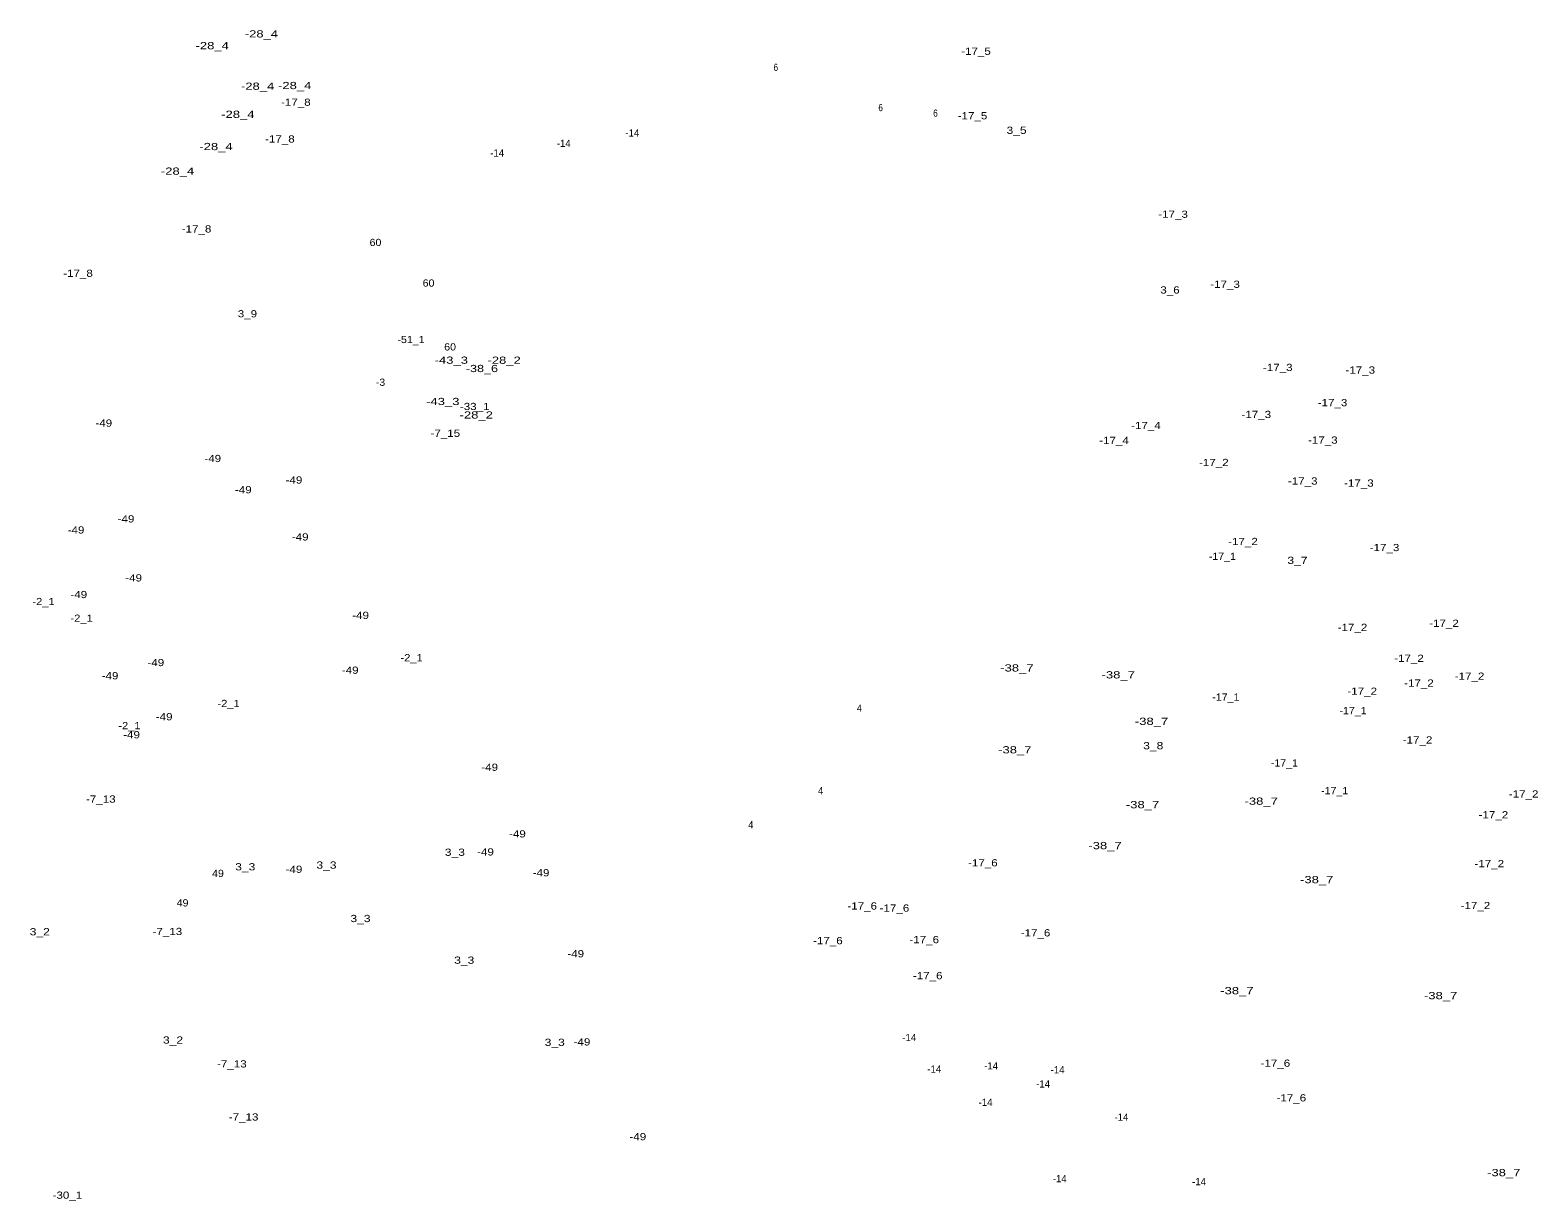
# Model space of a CAD drawing. Extents: x -663241 to -661169, y -1003538 to -1000899.
# Drawn here: x -662468 to -661633, y -1002888 to -1002239 of the extents above; entities that cross this region are included whole.
import ezdxf
from ezdxf.enums import TextEntityAlignment as Align

# ---------------------------------------------------------------- set-up
doc = ezdxf.new("R2010")
doc.units = 0
doc.header["$LTSCALE"] = 1.6
doc.layers.add('24', color=7, linetype='Continuous')

msp = doc.modelspace()

# ---------------------------------------------------------------- texts
at = {"layer": '24'}
for s, width, p in [('-28_4', 1.35, (-662340.16, -1002242.99)), ('-28_4', 1.35, (-662367.43, -1002249.52)), ('-17_5', 1.2, (-661944.33, -1002252.63)), ('6', 0.85, (-662055.2, -1002261.52)), ('-28_4', 1.35, (-662342.28, -1002271.99)), ('-28_4', 1.35, (-662321.73, -1002271.61)), ('-28_4', 1.35, (-662353.22, -1002287.55)), ('-17_8', 1.2, (-662321.11, -1002280.85)), ('6', 0.85, (-661997.15, -1002283.83)), ('6', 0.85, (-661966.78, -1002286.9)), ('-17_5', 1.2, (-661946.25, -1002288.36)), ('-17_8', 1.2, (-662329.94, -1002301.22)), ('3_5', 1.25, (-661921.84, -1002296.42)), ('-28_4', 1.35, (-662365.32, -1002305.42)), ('-28_4', 1.35, (-662386.63, -1002319.05)), ('-17_3', 1.2, (-661835.14, -1002342.92)), ('-17_8', 1.2, (-662376.11, -1002351.06)), ('60', 1.1, (-662276.99, -1002358.55)), ('-17_8', 1.2, (-662441.78, -1002375.65)), ('60', 1.1, (-662247.581, -1002381.05)), ('3_6', 1.2, (-661836.85, -1002384.88)), ('-17_3', 1.2, (-661806.34, -1002381.72)), ('3_9', 1.2, (-662347.919, -1002398.08)), ('-51_1', 1.1, (-662257.29, -1002412.34)), ('60', 1.1, (-662235.66, -1002416.44)), ('-43_3', 1.35, (-662234.99, -1002423.79)), ('-38_6', 1.3, (-662218.01, -1002428.41)), ('-28_2', 1.35, (-662205.72, -1002423.81)), ('-17_3', 1.2, (-661777.15, -1002427.82)), ('-17_3', 1.2, (-661731.45, -1002429.27)), ('-3', 1.1, (-662274.22, -1002436.01)), ('-43_3', 1.35, (-662239.7, -1002446.68)), ('-28_2', 1.35, (-662221.169, -1002454.15)), ('-33_1', 1.2, (-662222.03, -1002449.45)), ('-17_3', 1.2, (-661789.05, -1002453.86)), ('-17_3', 1.2, (-661746.81, -1002447.33)), ('-49', 1.2, (-662427.49, -1002458.65)), ('-17_4', 1.2, (-661850.18, -1002459.97)), ('-7_15', 1.2, (-662238.3, -1002464.29)), ('-17_4', 1.2, (-661867.85, -1002468.23)), ('-17_3', 1.2, (-661752.19, -1002468.07)), ('-49', 1.2, (-662367.13, -1002478.27)), ('-17_2', 1.2, (-661812.56, -1002480.47)), ('-49', 1.2, (-662350.211, -1002495.57)), ('-49', 1.2, (-662322.14, -1002490.19)), ('-17_3', 1.2, (-661763.33, -1002490.74)), ('-17_3', 1.2, (-661732.22, -1002491.89)), ('-49', 1.2, (-662415.191, -1002511.73)), ('-49', 1.2, (-662442.87, -1002517.88)), ('-49', 1.2, (-662318.681, -1002521.73)), ('-17_2', 1.2, (-661796.43, -1002524.26)), ('-17_3', 1.2, (-661718.01, -1002527.61)), ('-17_1', 1.1, (-661807.841, -1002532.48)), ('3_7', 1.25, (-661766.23, -1002534.71)), ('-49', 1.2, (-662410.961, -1002544.42)), ('-49', 1.2, (-662441.331, -1002553.65)), ('-2_1', 1.15, (-662460.9, -1002557.54)), ('-2_1', 1.15, (-662439.78, -1002566.76)), ('-49', 1.2, (-662285.24, -1002565.19)), ('-17_2', 1.2, (-661685.07, -1002569.57)), ('-17_2', 1.2, (-661735.76, -1002571.87)), ('-49', 1.2, (-662398.66, -1002591.34)), ('-49', 1.2, (-662291, -1002595.57)), ('-2_1', 1.15, (-662256.99, -1002588.65)), ('-38_7', 1.35, (-661921.66, -1002594.31)), ('-17_2', 1.2, (-661704.46, -1002588.97)), ('-49', 1.2, (-662424.03, -1002598.65)), ('-38_7', 1.35, (-661865.53, -1002598.15)), ('-17_2', 1.2, (-661698.95, -1002602.72)), ('-17_2', 1.2, (-661670.92, -1002598.88)), ('-17_1', 1.1, (-661805.921, -1002610.47)), ('-17_2', 1.2, (-661730.38, -1002607.22)), ('-49', 1.2, (-662394.041, -1002621.34)), ('-2_1', 1.15, (-662358.37, -1002614.01)), ('4', 0.95, (-662008.89, -1002616.6)), ('-17_1', 1.1, (-661735.451, -1002617.96)), ('-2_1', 1.15, (-662413.28, -1002626.3)), ('-38_7', 1.35, (-661847.08, -1002623.92)), ('-49', 1.2, (-662412.111, -1002631.34)), ('3_8', 1.25, (-661846.12, -1002637.39)), ('-17_2', 1.2, (-661699.72, -1002634.22)), ('-38_7', 1.35, (-661922.82, -1002639.69)), ('-49', 1.2, (-662213.721, -1002649.35)), ('-17_1', 1.1, (-661773.471, -1002646.96)), ('4', 0.95, (-662030.419, -1002662.37)), ('-17_1', 1.1, (-661745.63, -1002662.33)), ('-7_13', 1.2, (-662429.13, -1002666.97)), ('-38_7', 1.35, (-661852.07, -1002670.08)), ('-38_7', 1.35, (-661786.33, -1002668.15)), ('-17_2', 1.2, (-661640.96, -1002664.16)), ('-17_2', 1.2, (-661657.67, -1002675.68)), ('-49', 1.2, (-662198.341, -1002686.28)), ('4', 0.95, (-662069.059, -1002681.22)), ('3_3', 1.25, (-662233.01, -1002696.44)), ('-49', 1.2, (-662216.03, -1002696.28)), ('-38_7', 1.35, (-661872.84, -1002692.77)), ('3_3', 1.25, (-662349.12, -1002704.52)), ('3_3', 1.25, (-662304.14, -1002703.56)), ('-17_6', 1.2, (-661940.52, -1002702.31)), ('-17_2', 1.2, (-661659.97, -1002702.76)), ('49', 1.1, (-662364.24, -1002708.16)), ('-49', 1.2, (-662322.14, -1002705.89)), ('-49', 1.2, (-662185.27, -1002707.82)), ('-38_7', 1.35, (-661755.57, -1002711.62)), ('49', 1.1, (-662383.85, -1002724.5)), ('-17_6', 1.2, (-662007.36, -1002726.23)), ('-17_6', 1.2, (-661989.5, -1002727.38)), ('-17_2', 1.2, (-661667.65, -1002726)), ('3_3', 1.25, (-662285.3, -1002733.17)), ('3_2', 1.25, (-662462.96, -1002740.51)), ('-7_13', 1.2, (-662392.27, -1002740.35)), ('-17_6', 1.2, (-662026.37, -1002745.43)), ('-17_6', 1.2, (-661972.99, -1002744.86)), ('-17_6', 1.2, (-661911.34, -1002741.11)), ('-49', 1.2, (-662166.051, -1002752.7)), ('3_3', 1.25, (-662227.82, -1002756.25)), ('-17_6', 1.2, (-661971.07, -1002764.83)), ('-38_7', 1.35, (-661799.79, -1002773.15)), ('-38_7', 1.35, (-661686.94, -1002775.89)), ('3_2', 1.25, (-662389.14, -1002800.51)), ('3_3', 1.25, (-662177.68, -1002801.77)), ('-49', 1.2, (-662162.591, -1002801.55)), ('-7_13', 1.2, (-662356.55, -1002813.72)), ('-17_6', 1.2, (-661778.47, -1002813.33)), ('-17_6', 1.2, (-661769.64, -1002832.54)), ('-7_13', 1.2, (-662350.02, -1002843.13)), ('-49', 1.2, (-662131.64, -1002854.05)), ('-38_7', 1.35, (-661651.96, -1002873.97)), ('-30_1', 1.2, (-662447.65, -1002886.47))]:
    msp.add_text(s, height=4, dxfattribs=dict(at, width=width)).set_placement(p, align=Align.CENTER)
for p in [(-662172.7, -1002303.64), (-662134.69, -1002297.88), (-662209.57, -1002309.02), (-661981.27, -1002799.08), (-661967.45, -1002816.6), (-661935.96, -1002814.83), (-661899.1, -1002816.98), (-661907.16, -1002824.82), (-661939.03, -1002835.03), (-661863.77, -1002843.26), (-661897.94, -1002877.29), (-661820.76, -1002878.98)]:
    msp.add_text('-14', height=4, dxfattribs=at).set_placement(p, align=Align.CENTER)

doc.saveas('drawing.dxf')
